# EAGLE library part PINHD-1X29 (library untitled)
PIN HEADER
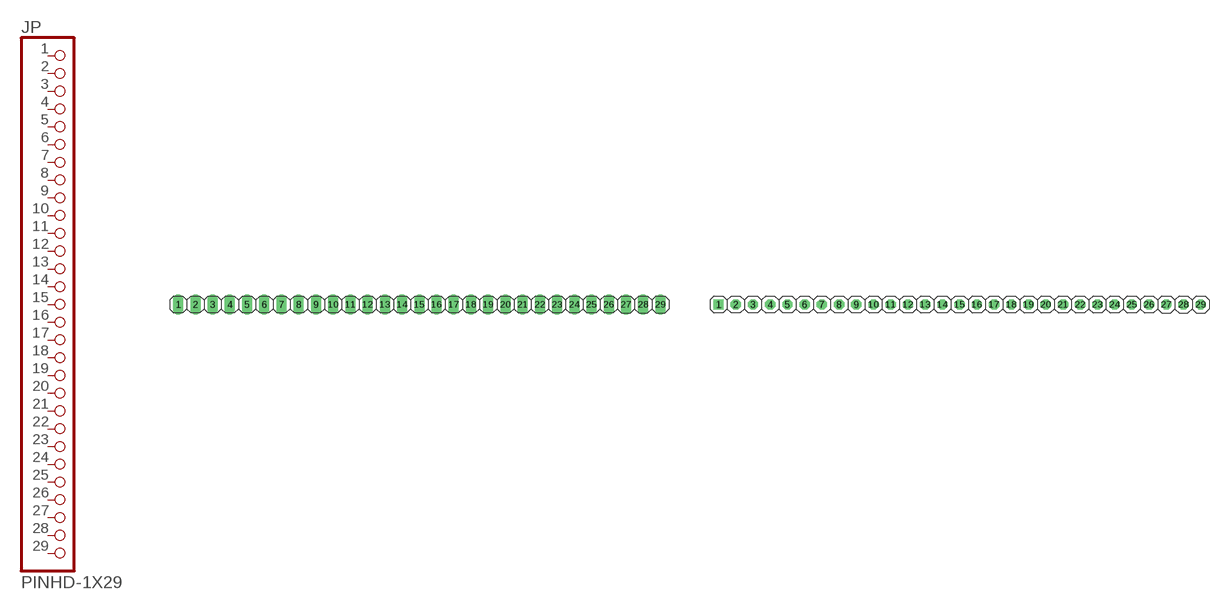
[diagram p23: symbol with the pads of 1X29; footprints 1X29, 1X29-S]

Designator prefix JP

## PINHD-1X29_2.54  [1X29]
1  1  pas
2  2  pas
3  3  pas
4  4  pas
5  5  pas
6  6  pas
7  7  pas
8  8  pas
9  9  pas
10  10  pas
11  11  pas
12  12  pas
13  13  pas
14  14  pas
15  15  pas
16  16  pas
17  17  pas
18  18  pas
19  19  pas
20  20  pas
21  21  pas
22  22  pas
23  23  pas
24  24  pas
25  25  pas
26  26  pas
27  27  pas
28  28  pas
29  29  pas

## PINHD-1X29_2.54-S  [1X29-S]
Pads as for 1X29

## PINHD-1X29_2.54-90°  [1X29/90]
Pads as for 1X29

## PINHD-1X29_2.54-90°-S  [1X29/90-S]
Pads as for 1X29

## PINHD-1X29_2.00  [1X29M]
Pads as for 1X29

## PINHD-1X29_2.54-SMD  [1X29SMD]
Pads as for 1X29

## PINHD-1X29_2.54-SMD-90°  [1X29SMD/90]
Pads as for 1X29

## Footprint 1X29 (pad centres in mm)
PIN HEADER - 2.54
drill 1.016 long: 1 -29.21,0; 2 -26.67,0; 3 -24.13,0; 4 -21.59,0; 5 -19.05,0; 6 -16.51,0; 7 -13.97,0; 8 -11.43,0; 9 -8.89,0; 10 -6.35,0; 11 -3.81,0; 12 -1.27,0; 13 1.27,0; 14 3.81,0; 15 6.35,0; 16 8.89,0; 17 11.43,0; 18 13.97,0; 19 16.51,0; 20 19.05,0; 21 21.59,0; 22 24.13,0; 23 26.67,0; 24 29.21,0; 25 31.75,0; 26 34.29,0; 27 36.83,0; 28 39.37,0; 29 41.91,0

## Footprint 1X29-S (pad centres in mm)
PIN HEADER - 2.54
drill 1.016 square: 1 -29.21,0
drill 1.016 octagon: 2 -26.67,0; 3 -24.13,0; 4 -21.59,0; 5 -19.05,0; 6 -16.51,0; 7 -13.97,0; 8 -11.43,0; 9 -8.89,0; 10 -6.35,0; 11 -3.81,0; 12 -1.27,0; 13 1.27,0; 14 3.81,0; 15 6.35,0; 16 8.89,0; 17 11.43,0; 18 13.97,0; 19 16.51,0; 20 19.05,0; 21 21.59,0; 22 24.13,0; 23 26.67,0; 24 29.21,0; 25 31.75,0; 26 34.29,0; 27 36.83,0; 28 39.37,0; 29 41.91,0

## Footprint 1X29/90 (pad centres in mm)
PIN HEADER - 2.54 90°
drill 1.016 long: 1 -24.13,-3.81; 2 -21.59,-3.81; 3 -19.05,-3.81; 4 -16.51,-3.81; 5 -13.97,-3.81; 6 -11.43,-3.81; 7 -8.89,-3.81; 8 -6.35,-3.81; 9 -3.81,-3.81; 10 -1.27,-3.81; 11 1.27,-3.81; 12 3.81,-3.81; 13 6.35,-3.81; 14 8.89,-3.81; 15 11.43,-3.81; 16 13.97,-3.81; 17 16.51,-3.81; 18 19.05,-3.81; 19 21.59,-3.81; 20 24.13,-3.81; 21 26.67,-3.81; 22 29.21,-3.81; 23 31.75,-3.81; 24 34.29,-3.81; 25 36.83,-3.81; 26 39.37,-3.81; 27 41.91,-3.81; 28 44.45,-3.81; 29 46.99,-3.81

## Footprint 1X29/90-S (pad centres in mm)
PIN HEADER - 2.54 90°
drill 1.016 square: 1 -24.13,-3.81
drill 1.016 octagon: 2 -21.59,-3.81; 3 -19.05,-3.81; 4 -16.51,-3.81; 5 -13.97,-3.81; 6 -11.43,-3.81; 7 -8.89,-3.81; 8 -6.35,-3.81; 9 -3.81,-3.81; 10 -1.27,-3.81; 11 1.27,-3.81; 12 3.81,-3.81; 13 6.35,-3.81; 14 8.89,-3.81; 15 11.43,-3.81; 16 13.97,-3.81; 17 16.51,-3.81; 18 19.05,-3.81; 19 21.59,-3.81; 20 24.13,-3.81; 21 26.67,-3.81; 22 29.21,-3.81; 23 31.75,-3.81; 24 34.29,-3.81; 25 36.83,-3.81; 26 39.37,-3.81; 27 41.91,-3.81; 28 44.45,-3.81; 29 46.99,-3.81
